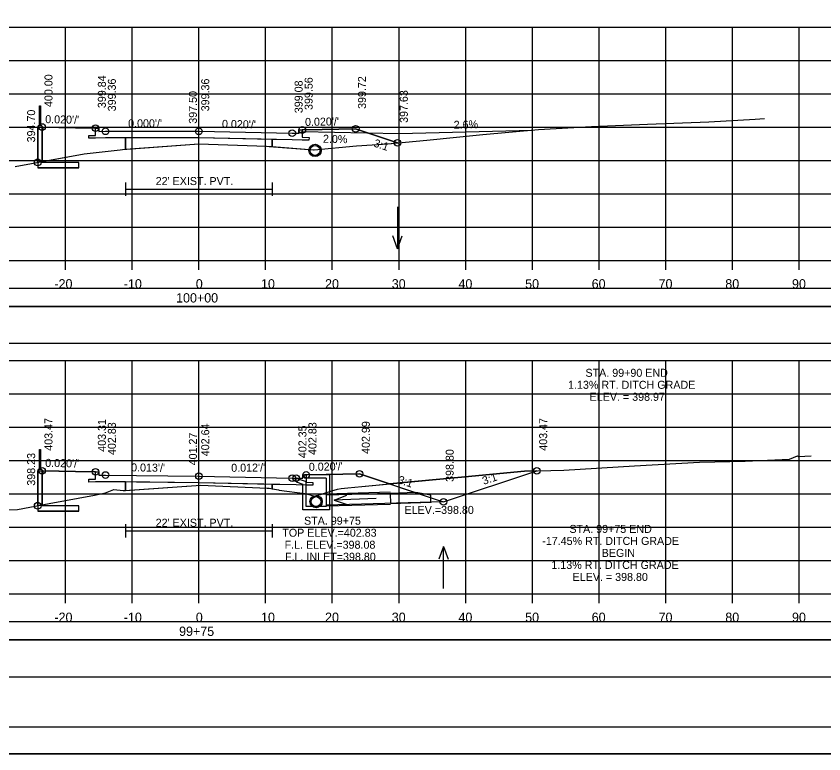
# Model space of a CAD drawing. Extents: x -37291014 to -37290680, y -936053 to -933067.
# Drawn here: x -37290870.5 to -37290749.4, y -935840 to -935729.3 of the extents above; entities that cross this region are included whole.
import ezdxf

# ---------------------------------------------------------------- set-up
doc = ezdxf.new("R2010")
doc.units = 0
for name, color, linetype in [('Default', 7, 'Continuous'), ('R_Alt Surface', 7, 'Continuous'), ('R_Axis', 7, 'Continuous'), ('R_Axis Annot', 7, 'Continuous'), ('R_Border', 7, 'Continuous'), ('R_Contours', 7, 'Continuous'), ('R_Drive', 7, 'Continuous'), ('R_Exist Surface', 7, 'Continuous'), ('R_Fin Surface', 7, 'Continuous'), ('R_Grid', 7, 'Continuous'), ('R_No Plot', 7, 'Continuous'), ('R_Water', 7, 'Continuous'), ('R_Water Annot', 7, 'Continuous'), ('R_Xsect Elev', 7, 'Continuous'), ('R_Xsect Slope', 7, 'Continuous')]:
    doc.layers.add(name, color=color, linetype=linetype)

msp = doc.modelspace()

# ---------------------------------------------------------------- linework, layer by layer
at = {"layer": 'Default'}
for p, q in [((-37290867.02, -935745.79), (-37290867.02, -935742.79)), ((-37290867.02, -935742.79), (-37290866.85, -935742.79)), ((-37290866.85, -935742.79), (-37290866.85, -935745.79)), ((-37290867.21, -935745.81), (-37290867.27, -935745.88)), ((-37290867.27, -935745.88), (-37290867.27, -935752.11)), ((-37290866.66, -935745.79), (-37290867.21, -935745.79)), ((-37290867.21, -935745.79), (-37290867.21, -935745.81)), ((-37290866.66, -935745.81), (-37290867.21, -935745.81)), ((-37290866.66, -935745.81), (-37290866.66, -935745.79)), ((-37290866.6, -935745.88), (-37290866.66, -935745.81)), ((-37290866.6, -935751.28), (-37290866.6, -935745.88)), ((-37290861.1, -935751.28), (-37290866.6, -935751.28)), ((-37290861.1, -935752.11), (-37290861.1, -935751.28)), ((-37290861.1, -935752.11), (-37290867.27, -935752.11)), ((-37290867.02, -935797.33), (-37290867.02, -935794.33)), ((-37290867.02, -935794.33), (-37290866.85, -935794.33)), ((-37290866.85, -935794.33), (-37290866.85, -935797.33)), ((-37290867.21, -935797.35), (-37290867.27, -935797.41)), ((-37290867.27, -935797.41), (-37290867.27, -935803.59)), ((-37290866.66, -935797.33), (-37290867.21, -935797.33)), ((-37290867.21, -935797.33), (-37290867.21, -935797.35)), ((-37290866.66, -935797.35), (-37290867.21, -935797.35)), ((-37290866.66, -935797.35), (-37290866.66, -935797.33)), ((-37290866.6, -935797.41), (-37290866.66, -935797.35)), ((-37290866.6, -935802.76), (-37290866.6, -935797.41)), ((-37290861.1, -935802.76), (-37290866.6, -935802.76)), ((-37290861.1, -935803.59), (-37290861.1, -935802.76)), ((-37290861.1, -935803.59), (-37290867.27, -935803.59))]:
    msp.add_line(p, q, dxfattribs=at)
for points in [[(-37290866.52, -935746.48), (-37290866.6, -935746.48), (-37290866.6, -935745.98), (-37290866.52, -935745.98), (-37290866.52, -935746.48)], [(-37290866.52, -935798.02), (-37290866.6, -935798.02), (-37290866.6, -935797.52), (-37290866.52, -935797.52), (-37290866.52, -935798.02)]]:
    msp.add_lwpolyline(points, dxfattribs=at)
for points in [[(-37290992.48, -935772.89), (-37290693.72, -935772.89), (-37290693.72, -935770.19), (-37290992.48, -935770.19)], [(-37290992.48, -935778.41), (-37290693.72, -935778.41), (-37290693.72, -935772.89), (-37290992.48, -935772.89)], [(-37290992.48, -935822.89), (-37290693.72, -935822.89), (-37290693.72, -935820.19), (-37290992.48, -935820.19)], [(-37290992.48, -935828.41), (-37290693.72, -935828.41), (-37290693.72, -935822.89), (-37290992.48, -935822.89)]]:
    msp.add_lwpolyline(points, close=True, dxfattribs=at)
at = {"layer": 'R_Alt Surface'}
for points in [[(-37290827.6, -935746.42), (-37290827.6, -935747.52), (-37290826.59, -935747.54), (-37290826.6, -935747.95), (-37290827.6, -935747.93), (-37290829.1, -935747.9), (-37290843.1, -935747.62), (-37290857.1, -935747.62), (-37290858.6, -935747.65), (-37290859.6, -935747.67), (-37290859.61, -935747.25), (-37290858.6, -935747.23), (-37290858.6, -935746.14)], [(-37290854.1, -935754.28), (-37290854.1, -935756.28)], [(-37290832.1, -935754.28), (-37290832.1, -935756.28)], [(-37290854.1, -935755.28), (-37290832.1, -935755.28)], [(-37290827.03, -935798.15), (-37290827.03, -935799.25), (-37290826.02, -935799.27), (-37290826.03, -935799.68), (-37290827.03, -935799.66), (-37290828.53, -935799.63), (-37290843.1, -935799.34), (-37290857.1, -935799.16), (-37290858.6, -935799.19), (-37290859.6, -935799.21), (-37290859.61, -935798.79), (-37290858.6, -935798.77), (-37290858.6, -935797.68)], [(-37290854.1, -935805.51), (-37290854.1, -935807.51)], [(-37290832.1, -935805.51), (-37290832.1, -935807.51)], [(-37290854.1, -935806.51), (-37290832.1, -935806.51)]]:
    msp.add_lwpolyline(points, dxfattribs=at)
at = {"layer": 'R_Axis'}
for p, q in [((-37290993.1, -935765.99), (-37290693.1, -935765.99)), ((-37290863.1, -935767.39), (-37290863.1, -935765.99)), ((-37290853.1, -935767.39), (-37290853.1, -935765.99)), ((-37290843.1, -935767.39), (-37290843.1, -935765.99)), ((-37290833.1, -935767.39), (-37290833.1, -935765.99)), ((-37290823.1, -935767.39), (-37290823.1, -935765.99)), ((-37290813.1, -935767.39), (-37290813.1, -935765.99)), ((-37290803.1, -935767.39), (-37290803.1, -935765.99)), ((-37290793.1, -935767.39), (-37290793.1, -935765.99)), ((-37290783.1, -935767.39), (-37290783.1, -935765.99)), ((-37290773.1, -935767.39), (-37290773.1, -935765.99)), ((-37290763.1, -935767.39), (-37290763.1, -935765.99)), ((-37290753.1, -935767.39), (-37290753.1, -935765.99)), ((-37290993.1, -935815.99), (-37290693.1, -935815.99)), ((-37290863.1, -935817.39), (-37290863.1, -935815.99)), ((-37290853.1, -935817.39), (-37290853.1, -935815.99)), ((-37290843.1, -935817.39), (-37290843.1, -935815.99)), ((-37290833.1, -935817.39), (-37290833.1, -935815.99)), ((-37290823.1, -935817.39), (-37290823.1, -935815.99)), ((-37290813.1, -935817.39), (-37290813.1, -935815.99)), ((-37290803.1, -935817.39), (-37290803.1, -935815.99)), ((-37290793.1, -935817.39), (-37290793.1, -935815.99)), ((-37290783.1, -935817.39), (-37290783.1, -935815.99)), ((-37290773.1, -935817.39), (-37290773.1, -935815.99)), ((-37290763.1, -935817.39), (-37290763.1, -935815.99)), ((-37290753.1, -935817.39), (-37290753.1, -935815.99))]:
    msp.add_line(p, q, dxfattribs=at)
at = {"layer": 'R_Border'}
msp.add_line((-37290684.92, -935835.99), (-37291001.1, -935835.99), dxfattribs=at)
at = {"layer": 'R_Contours'}
for p, q in [((-37290866.6, -935746.48), (-37290866.6, -935751.16)), ((-37290843.1, -935747.62), (-37290854.1, -935747.62)), ((-37290854.1, -935747.62), (-37290854.1, -935749.32)), ((-37290854.1, -935749.32), (-37290854.1, -935747.62)), ((-37290832.1, -935747.84), (-37290843.1, -935747.62)), ((-37290832.1, -935748.92), (-37290832.1, -935747.84)), ((-37290832.1, -935747.84), (-37290832.1, -935748.92)), ((-37290832.1, -935748.92), (-37290825.91, -935749.4)), ((-37290866.6, -935751.16), (-37290867.27, -935751.28)), ((-37290866.6, -935751.28), (-37290866.6, -935751.16)), ((-37290861.1, -935751.28), (-37290866.6, -935751.28)), ((-37290861.1, -935752.11), (-37290861.1, -935751.28)), ((-37290867.27, -935752.11), (-37290861.1, -935752.11)), ((-37290866.6, -935798.02), (-37290866.6, -935802.63)), ((-37290814.51, -935799.5), (-37290819.03, -935797.99)), ((-37290854.1, -935799.2), (-37290854.1, -935800.48)), ((-37290854.1, -935800.48), (-37290854.1, -935799.2)), ((-37290832.1, -935800.23), (-37290832.1, -935799.56)), ((-37290832.1, -935799.56), (-37290832.1, -935800.23)), ((-37290814.51, -935799.5), (-37290806.93, -935802.03)), ((-37290866.6, -935802.63), (-37290867.27, -935802.76)), ((-37290866.6, -935802.76), (-37290866.6, -935802.63)), ((-37290861.1, -935802.76), (-37290866.6, -935802.76)), ((-37290861.1, -935803.59), (-37290861.1, -935802.76)), ((-37290867.27, -935803.59), (-37290861.1, -935803.59))]:
    msp.add_line(p, q, dxfattribs=at)
for points in [[(-37290866.52, -935745.98), (-37290866.52, -935746.48), (-37290866.6, -935746.48)], [(-37290858.6, -935746.14), (-37290861.6, -935746.08), (-37290866.52, -935745.98)], [(-37290854.1, -935747.62), (-37290857.1, -935747.62), (-37290858.6, -935747.65), (-37290859.6, -935747.67), (-37290859.61, -935747.25), (-37290858.6, -935747.23), (-37290858.6, -935746.14)], [(-37290827.6, -935746.42), (-37290827.6, -935747.52), (-37290826.59, -935747.54), (-37290826.6, -935747.95), (-37290827.6, -935747.93), (-37290829.1, -935747.9), (-37290832.1, -935747.84)], [(-37290813.33, -935748.36), (-37290819.6, -935746.26), (-37290824.6, -935746.36), (-37290827.6, -935746.42)], [(-37290854.1, -935749.32), (-37290843.1, -935748.48), (-37290832.99, -935748.86), (-37290832.56, -935748.88), (-37290832.1, -935748.92)], [(-37290825.91, -935749.4), (-37290825.83, -935749.4), (-37290819.48, -935748.82), (-37290814.8, -935748.5), (-37290813.33, -935748.36)], [(-37290813.33, -935748.36), (-37290813.33, -935748.36)], [(-37290866.6, -935751.16), (-37290860.31, -935750), (-37290854.9, -935749.39), (-37290854.56, -935749.36), (-37290854.1, -935749.32)], [(-37290867.27, -935751.28), (-37290867.27, -935751.28), (-37290867.27, -935752.11)], [(-37290866.52, -935797.52), (-37290866.52, -935798.02), (-37290866.6, -935798.02)], [(-37290858.6, -935797.68), (-37290861.6, -935797.62), (-37290866.52, -935797.52)], [(-37290854.1, -935799.2), (-37290857.1, -935799.16), (-37290858.6, -935799.19), (-37290859.6, -935799.21), (-37290859.61, -935798.79), (-37290858.6, -935798.77), (-37290858.6, -935797.68)], [(-37290827.03, -935798.15), (-37290827.03, -935799.25), (-37290826.02, -935799.27), (-37290826.03, -935799.68), (-37290827.03, -935799.66), (-37290828.53, -935799.63), (-37290832.1, -935799.56)], [(-37290819.03, -935797.99), (-37290824.03, -935798.09), (-37290827.03, -935798.15)], [(-37290792.44, -935797.52), (-37290794.28, -935797.57), (-37290804.26, -935798.52), (-37290807.51, -935798.83), (-37290814.51, -935799.5)], [(-37290806.93, -935802.03), (-37290806.45, -935802.19), (-37290792.44, -935797.52)], [(-37290832.1, -935799.56), (-37290843.1, -935799.34), (-37290854.1, -935799.2)], [(-37290854.1, -935800.48), (-37290842.82, -935799.69), (-37290832.85, -935800.11), (-37290832.57, -935800.12), (-37290832.1, -935800.23)], [(-37290832.1, -935800.23), (-37290832.05, -935800.25), (-37290831.15, -935800.4), (-37290831.08, -935800.42), (-37290827.24, -935800.92), (-37290825.69, -935801.34), (-37290823.17, -935800.51), (-37290822.33, -935800.29), (-37290821.77, -935800.2), (-37290820.77, -935800.1), (-37290818.69, -935799.9), (-37290814.51, -935799.5)], [(-37290866.6, -935802.63), (-37290865.57, -935802.44), (-37290858.77, -935801.18), (-37290857.08, -935800.85), (-37290855.87, -935800.34), (-37290854.45, -935800.48), (-37290854.4, -935800.5), (-37290854.19, -935800.49), (-37290854.1, -935800.48)], [(-37290867.27, -935802.76), (-37290867.27, -935802.76), (-37290867.27, -935803.59)]]:
    msp.add_lwpolyline(points, dxfattribs=at)
at = {"layer": 'R_Drive'}
for p, q in [((-37290813.07, -935746.97), (-37290793.1, -935746.45)), ((-37290828.1, -935746.92), (-37290827.6, -935746.67)), ((-37290827.6, -935746.67), (-37290813.07, -935746.97))]:
    msp.add_line(p, q, dxfattribs=at)
at = {"layer": 'R_Exist Surface'}
for points in [[(-37290870.65, -935751.9), (-37290860.31, -935750), (-37290854.9, -935749.39), (-37290854.56, -935749.36), (-37290843.1, -935748.48), (-37290843.1, -935748.48), (-37290843.1, -935748.48), (-37290832.99, -935748.86), (-37290832.56, -935748.88), (-37290825.91, -935749.4), (-37290825.83, -935749.4), (-37290819.48, -935748.82), (-37290814.8, -935748.5), (-37290808.93, -935747.93), (-37290800.56, -935747.12), (-37290792.19, -935746.36), (-37290784.27, -935745.89), (-37290775.87, -935745.55), (-37290766.67, -935745.18), (-37290759.73, -935744.78), (-37290758.29, -935744.72)], [(-37290871.85, -935803.39), (-37290870.31, -935803.32), (-37290865.57, -935802.44), (-37290858.77, -935801.18), (-37290857.08, -935800.85), (-37290855.87, -935800.34), (-37290854.45, -935800.48), (-37290854.4, -935800.5), (-37290854.19, -935800.49), (-37290842.82, -935799.69), (-37290832.85, -935800.11), (-37290832.57, -935800.12), (-37290832.05, -935800.25), (-37290831.15, -935800.4), (-37290831.08, -935800.42), (-37290827.24, -935800.92), (-37290825.69, -935801.34), (-37290823.17, -935800.51), (-37290822.33, -935800.29), (-37290821.77, -935800.2), (-37290820.77, -935800.1), (-37290818.69, -935799.9), (-37290807.51, -935798.83), (-37290804.26, -935798.52), (-37290794.28, -935797.57), (-37290788.4, -935797.41), (-37290777.8, -935796.79), (-37290768.07, -935796.21), (-37290761.23, -935796.07), (-37290754.54, -935795.8), (-37290753.35, -935795.29), (-37290753.23, -935795.36), (-37290751.32, -935795.28)]]:
    msp.add_lwpolyline(points, dxfattribs=at)
at = {"layer": 'R_Fin Surface'}
for points in [[(-37290867.27, -935751.28), (-37290867.27, -935745.98), (-37290866.6, -935745.98), (-37290861.6, -935746.08), (-37290858.6, -935746.14), (-37290858.1, -935746.14), (-37290858.1, -935746.64), (-37290857.1, -935746.62), (-37290843.1, -935746.62), (-37290829.1, -935746.9), (-37290828.1, -935746.92), (-37290828.1, -935746.42), (-37290827.6, -935746.42), (-37290824.6, -935746.36), (-37290819.6, -935746.26), (-37290813.33, -935748.36)], [(-37290867.27, -935802.76), (-37290867.27, -935797.52), (-37290866.6, -935797.52), (-37290861.6, -935797.62), (-37290858.6, -935797.68), (-37290858.1, -935797.68), (-37290858.1, -935798.18), (-37290857.1, -935798.16), (-37290843.1, -935798.34), (-37290829.1, -935798.62), (-37290828.53, -935798.63), (-37290827.54, -935798.65), (-37290827.53, -935798.15), (-37290827.03, -935798.15), (-37290824.03, -935798.09), (-37290819.03, -935797.99), (-37290806.93, -935802.03), (-37290806.45, -935802.19), (-37290792.44, -935797.52)]]:
    msp.add_lwpolyline(points, dxfattribs=at)
at = {"layer": 'R_Grid'}
for p, q in [((-37290993.1, -935730.99), (-37290693.1, -935730.99)), ((-37290863.1, -935765.99), (-37290863.1, -935730.99)), ((-37290853.1, -935765.99), (-37290853.1, -935730.99)), ((-37290843.1, -935765.99), (-37290843.1, -935730.99)), ((-37290833.1, -935765.99), (-37290833.1, -935730.99)), ((-37290823.1, -935765.99), (-37290823.1, -935730.99)), ((-37290813.1, -935765.99), (-37290813.1, -935730.99)), ((-37290803.1, -935765.99), (-37290803.1, -935730.99)), ((-37290793.1, -935765.99), (-37290793.1, -935730.99)), ((-37290783.1, -935765.99), (-37290783.1, -935730.99)), ((-37290773.1, -935765.99), (-37290773.1, -935730.99)), ((-37290763.1, -935765.99), (-37290763.1, -935730.99)), ((-37290753.1, -935765.99), (-37290753.1, -935730.99)), ((-37290993.1, -935735.99), (-37290693.1, -935735.99)), ((-37290993.1, -935740.99), (-37290693.1, -935740.99)), ((-37290993.1, -935745.99), (-37290693.1, -935745.99)), ((-37290993.1, -935750.99), (-37290693.1, -935750.99)), ((-37290993.1, -935755.99), (-37290693.1, -935755.99)), ((-37290993.1, -935760.99), (-37290693.1, -935760.99)), ((-37290993.1, -935765.99), (-37290693.1, -935765.99)), ((-37290993.1, -935780.99), (-37290693.1, -935780.99)), ((-37290863.1, -935815.99), (-37290863.1, -935780.99)), ((-37290853.1, -935815.99), (-37290853.1, -935780.99)), ((-37290843.1, -935815.99), (-37290843.1, -935780.99)), ((-37290833.1, -935815.99), (-37290833.1, -935780.99)), ((-37290823.1, -935815.99), (-37290823.1, -935780.99)), ((-37290813.1, -935815.99), (-37290813.1, -935780.99)), ((-37290803.1, -935815.99), (-37290803.1, -935780.99)), ((-37290793.1, -935815.99), (-37290793.1, -935780.99)), ((-37290783.1, -935815.99), (-37290783.1, -935780.99)), ((-37290773.1, -935815.99), (-37290773.1, -935780.99)), ((-37290763.1, -935815.99), (-37290763.1, -935780.99)), ((-37290753.1, -935815.99), (-37290753.1, -935780.99)), ((-37290993.1, -935785.99), (-37290693.1, -935785.99)), ((-37290993.1, -935790.99), (-37290693.1, -935790.99)), ((-37290993.1, -935795.99), (-37290693.1, -935795.99)), ((-37290993.1, -935800.99), (-37290693.1, -935800.99)), ((-37290993.1, -935805.99), (-37290693.1, -935805.99)), ((-37290993.1, -935810.99), (-37290693.1, -935810.99)), ((-37290993.1, -935815.99), (-37290693.1, -935815.99))]:
    msp.add_line(p, q, dxfattribs=at)
at = {"layer": 'R_No Plot'}
for p, q in [((-37290814.43, -935800.75), (-37290824.04, -935801.02)), ((-37290814.38, -935802.58), (-37290824.04, -935802.85)), ((-37291013.5, -935839.96), (-37290680.17, -935839.96))]:
    msp.add_line(p, q, dxfattribs=at)
for points in [[(-37291013.51, -935626.63), (-37290680.17, -935626.63), (-37290680.17, -935839.97), (-37291013.51, -935839.97)], [(-37290767.18, -935630.53), (-37290747.56, -935630.53), (-37290747.56, -935640.41), (-37290731.45, -935640.41), (-37290708.25, -935640.41), (-37290708.25, -935664.74), (-37290684.92, -935664.74), (-37290684.92, -935835.99), (-37291001.1, -935835.99), (-37291001.1, -935630.53)]]:
    msp.add_lwpolyline(points, close=True, dxfattribs=at)
for centre, radius in [((-37290866.6, -935745.98), 0.5), ((-37290858.6, -935746.14), 0.5), ((-37290857.1, -935746.62), 0.5), ((-37290843.1, -935746.62), 0.5), ((-37290829.1, -935746.9), 0.5), ((-37290829.1, -935746.9), 0.5), ((-37290827.6, -935746.42), 0.5), ((-37290819.6, -935746.26), 0.5), ((-37290825.69, -935749.48), 0.917), ((-37290813.33, -935748.36), 0.5), ((-37290867.27, -935751.28), 0.5), ((-37290866.6, -935797.52), 0.5), ((-37290858.6, -935797.68), 0.5), ((-37290792.44, -935797.52), 0.5), ((-37290857.1, -935798.16), 0.5), ((-37290843.1, -935798.34), 0.5), ((-37290829.1, -935798.62), 0.5), ((-37290828.53, -935798.63), 0.5), ((-37290827.03, -935798.15), 0.5), ((-37290819.03, -935797.99), 0.5), ((-37290867.27, -935802.76), 0.5), ((-37290825.54, -935802.15), 0.917), ((-37290806.45, -935802.19), 0.5)]:
    msp.add_circle(centre, radius, dxfattribs=at)
at = {"layer": 'R_Water'}
for p, q in [((-37290828.54, -935798.63), (-37290827.04, -935799.15)), ((-37290827.37, -935798.32), (-37290827.29, -935798.15)), ((-37290827.37, -935798.32), (-37290827.04, -935798.65)), ((-37290823.54, -935798.15), (-37290827.29, -935798.15)), ((-37290824.04, -935798.65), (-37290827.04, -935798.65)), ((-37290828.54, -935799.16), (-37290827.54, -935799.51)), ((-37290827.54, -935799.65), (-37290827.54, -935799.51)), ((-37290827.04, -935799.65), (-37290827.04, -935799.15)), ((-37290814.43, -935800.91), (-37290824.04, -935801.18)), ((-37290806.45, -935802.19), (-37290824.04, -935802.68))]:
    msp.add_line(p, q, dxfattribs=at)
for points in [[(-37290828.54, -935799.16), (-37290828.54, -935798.63)], [(-37290823.54, -935798.15), (-37290823.54, -935803.4), (-37290825.54, -935803.4), (-37290827.54, -935803.4), (-37290827.54, -935799.65)], [(-37290824.04, -935798.65), (-37290824.04, -935802.9), (-37290825.54, -935802.9), (-37290827.04, -935802.9), (-37290827.04, -935799.65)]]:
    msp.add_lwpolyline(points, dxfattribs=at)
msp.add_lwpolyline([(-37290814.43, -935800.91), (-37290814.39, -935802.41), (-37290808.31, -935802.24), (-37290808.34, -935801.2), (-37290810.6, -935800.8)], close=True, dxfattribs=at)
for centre in [(-37290825.69, -935749.48), (-37290825.54, -935802.15)]:
    msp.add_circle(centre, 0.75, dxfattribs=at)
at = {"layer": 'R_Water Annot'}
for p, q in [((-37290813.33, -935757.94), (-37290813.33, -935764.22)), ((-37290813.33, -935764.22), (-37290814.03, -935762.3)), ((-37290813.33, -935764.22), (-37290812.63, -935762.3)), ((-37290822.81, -935801.94), (-37290820.91, -935801.17)), ((-37290816.53, -935801.7), (-37290822.81, -935801.94)), ((-37290822.81, -935801.94), (-37290820.86, -935802.56)), ((-37290806.45, -935808.87), (-37290807.15, -935810.79)), ((-37290806.45, -935815.15), (-37290806.45, -935808.87)), ((-37290806.45, -935808.87), (-37290805.75, -935810.79))]:
    msp.add_line(p, q, dxfattribs=at)
at = {"layer": 'R_Xsect Elev'}
for p, q in [((-37290843.1, -935748.48), (-37290843.1, -935738.48)), ((-37290843.1, -935799.71), (-37290843.1, -935789.71))]:
    msp.add_line(p, q, dxfattribs=at)

# ---------------------------------------------------------------- texts
at = {"layer": 'R_Axis Annot'}
for s, p in [('-20', (-37290864.76, -935770.19)), ('-10', (-37290854.36, -935770.19)), ('0', (-37290843.56, -935770.19)), ('10', (-37290833.79, -935770.19)), ('20', (-37290824.19, -935770.19)), ('30', (-37290814.19, -935770.19)), ('40', (-37290804.19, -935770.19)), ('50', (-37290794.19, -935770.19)), ('60', (-37290784.22, -935770.19)), ('70', (-37290774.19, -935770.19)), ('80', (-37290764.19, -935770.19)), ('90', (-37290754.19, -935770.19)), ('100+00', (-37290846.52, -935772.29)), ('-20', (-37290864.76, -935820.19)), ('-10', (-37290854.36, -935820.19)), ('0', (-37290843.56, -935820.19)), ('10', (-37290833.79, -935820.19)), ('20', (-37290824.19, -935820.19)), ('30', (-37290814.19, -935820.19)), ('40', (-37290804.19, -935820.19)), ('50', (-37290794.19, -935820.19)), ('60', (-37290784.22, -935820.19)), ('70', (-37290774.19, -935820.19)), ('80', (-37290764.19, -935820.19)), ('90', (-37290754.19, -935820.19)), ('99+75', (-37290846.07, -935822.29))]:
    msp.add_text(s, height=1.4, dxfattribs=at).set_placement(p)
at = {"layer": 'R_Water'}
for p in [(-37290849.58, -935754.68), (-37290849.58, -935805.91)]:
    msp.add_text("22' EXIST. PVT.", height=1.2, dxfattribs=at).set_placement(p)
at = {"layer": 'R_Water Annot'}
for s, p in [('STA. 99+75', (-37290827.34, -935805.61)), ('TOP ELEV.=402.83', (-37290830.6, -935807.41)), ('F.L. ELEV.=398.08', (-37290830.25, -935809.21)), ('F.L. INLET=398.80', (-37290830.19, -935811.01))]:
    msp.add_text(s, height=1.2, dxfattribs=at).set_placement(p)
at = {"layer": 'R_Xsect Elev'}
for s, rotation, p in [('400.00', 90, (-37290865.05, -935742.98)), ('399.84', 90, (-37290857.05, -935743.14)), ('399.36', 90, (-37290855.55, -935743.62)), ('399.36', 90, (-37290841.55, -935743.62)), ('399.08', 90, (-37290827.55, -935743.9)), ('399.56', 90, (-37290826.05, -935743.42)), ('399.72', 90, (-37290818.05, -935743.26)), ('397.63', 90, (-37290811.78, -935745.36)), ('397.50', 90, (-37290843.4, -935745.48)), ('394.70', 90, (-37290867.65, -935748.28)), ('2.6%', 1.4894, (-37290804.89, -935746.25)), ('2.0%', 358.8542, (-37290824.51, -935748.33)), ('403.47', 90, (-37290865.05, -935794.52)), ('403.31', 90, (-37290857.05, -935794.68)), ('402.99', 90, (-37290817.48, -935794.99)), ('403.47', 90, (-37290790.89, -935794.52)), ('402.83', 90, (-37290855.55, -935795.16)), ('402.64', 90, (-37290841.55, -935795.34)), ('402.35', 90, (-37290826.98, -935795.63)), ('402.83', 90, (-37290825.48, -935795.15)), ('401.27', 90, (-37290843.4, -935796.71)), ('398.23', 90, (-37290867.65, -935799.76)), ('398.80', 90, (-37290804.9, -935799.19))]:
    msp.add_text(s, height=1.2, rotation=rotation, dxfattribs=at).set_placement(p)
for s, p in [('STA. 99+90 END ', (-37290785.15, -935783.43)), ('1.13% RT. DITCH GRADE', (-37290787.76, -935785.23)), ('ELEV. = 398.97', (-37290784.53, -935787.03)), ('ELEV.=398.80', (-37290812.28, -935803.99)), ('STA. 99+75 END', (-37290787.56, -935806.84)), ('-17.45% RT. DITCH GRADE', (-37290791.63, -935808.64)), ('BEGIN', (-37290782.72, -935810.44)), ('1.13% RT. DITCH GRADE', (-37290790.26, -935812.24)), ('ELEV. = 398.80', (-37290787.08, -935814.04))]:
    msp.add_text(s, height=1.2, dxfattribs=at).set_placement(p)
at = {"layer": 'R_Xsect Slope'}
for s, rotation, p in [("0.020'/'", 358.8542, (-37290866.15, -935745.39)), ("0.000'/'", 359.9878, (-37290853.71, -935746.02)), ("0.020'/'", 358.8542, (-37290839.65, -935746.09)), ("0.020'/'", 1.1458, (-37290827.18, -935745.82)), ('3:1', 341.5668, (-37290817, -935748.87)), ("0.020'/'", 358.8542, (-37290866.15, -935796.93)), ("0.020'/'", 1.1458, (-37290826.61, -935797.54)), ("0.013'/'", 359.2435, (-37290853.27, -935797.61)), ("0.012'/'", 0.6727, (-37290838.25, -935797.68)), ('3:1', 341.5668, (-37290813.37, -935799.35)), ('3:1', 18.4332, (-37290800.39, -935799.64))]:
    msp.add_text(s, height=1.2, rotation=rotation, dxfattribs=at).set_placement(p)

doc.saveas('drawing.dxf')
